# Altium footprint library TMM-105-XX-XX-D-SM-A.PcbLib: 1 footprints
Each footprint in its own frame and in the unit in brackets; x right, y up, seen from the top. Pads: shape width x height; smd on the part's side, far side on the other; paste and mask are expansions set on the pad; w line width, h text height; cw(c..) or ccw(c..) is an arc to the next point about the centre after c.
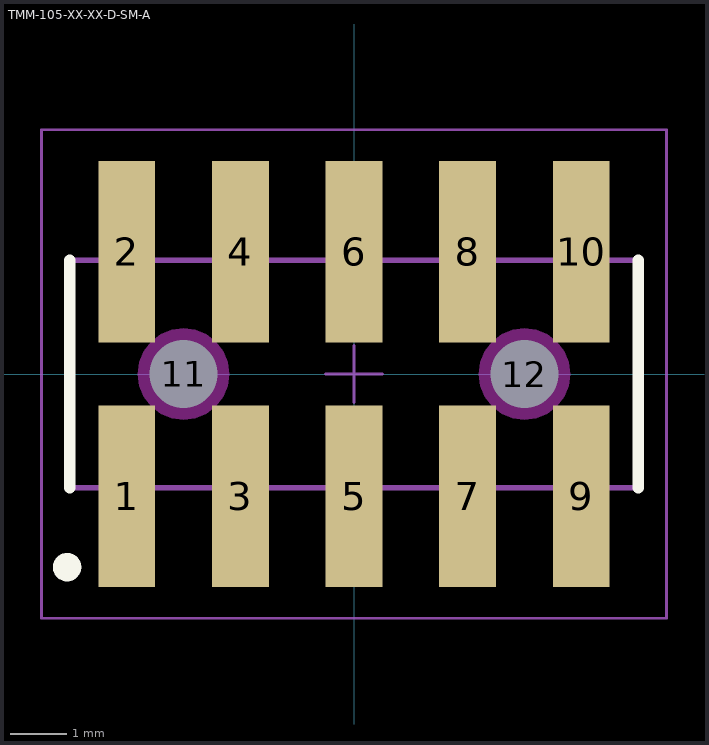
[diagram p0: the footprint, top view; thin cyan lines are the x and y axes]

## TMM-105-XX-XX-D-SM-A [mm] "2.00mm pitch, 10 pin, terminal strip; double row, w/alignment pins, SMT"
height 2.77
pads (12):
  rect 1x3.2 smd mask+0: 1(-4,-2.15) 2(-4,2.15) 3(-2,-2.15) 4(-2,2.15) 5(0,-2.15) 6(0,2.15) 7(2,-2.15) 8(2,2.15) 9(4,-2.15) 10(4,2.15)
  round 1 hole 1.2 unplated mask+0: 11(-3,0) 12(3,0)
Top Overlay:
  circle w0.25: c-5.05,-3.4 r0.125
  lines w0.2: -5,-2 -5,2 ; 5,-2 5,2
Keep-Out Layer:
  pour cut-out: -2.193,0 -2.221,0.209 -2.301,0.403 -2.429,0.571 -2.597,0.699 -2.791,0.779 -3,0.807 -3.209,0.779 -3.403,0.699 -3.571,0.571 -3.699,0.403 -3.779,0.209 -3.807,0 -3.779,-0.209 -3.699,-0.403 -3.571,-0.571 -3.403,-0.699 -3.209,-0.779 -3,-0.807 -2.791,-0.779 -2.597,-0.699 -2.429,-0.571 -2.301,-0.403 -2.221,-0.209
  pour cut-out: 3.807,0 3.779,0.209 3.699,0.403 3.571,0.571 3.403,0.699 3.209,0.779 3,0.807 2.791,0.779 2.597,0.699 2.429,0.571 2.301,0.403 2.221,0.209 2.193,0 2.221,-0.209 2.301,-0.403 2.429,-0.571 2.597,-0.699 2.791,-0.779 3,-0.807 3.209,-0.779 3.403,-0.699 3.571,-0.571 3.699,-0.403 3.779,-0.209
Mechanical 12:
  lines w0.001: -5,-2 5,-2 5,2 -5,2 -5,-2
Mechanical 13:
  lines w0.1: -5,-2 5,-2 5,2 -5,2 -5,-2
  text ".Designator" at 0,-0.127 h1.52
Mechanical 15:
  lines w0.05: -0.5,0 0.5,0 ; 0,-0.5 0,0.5 ; -5.5,-4.3 5.5,-4.3 5.5,4.3 -5.5,4.3 -5.5,-4.3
